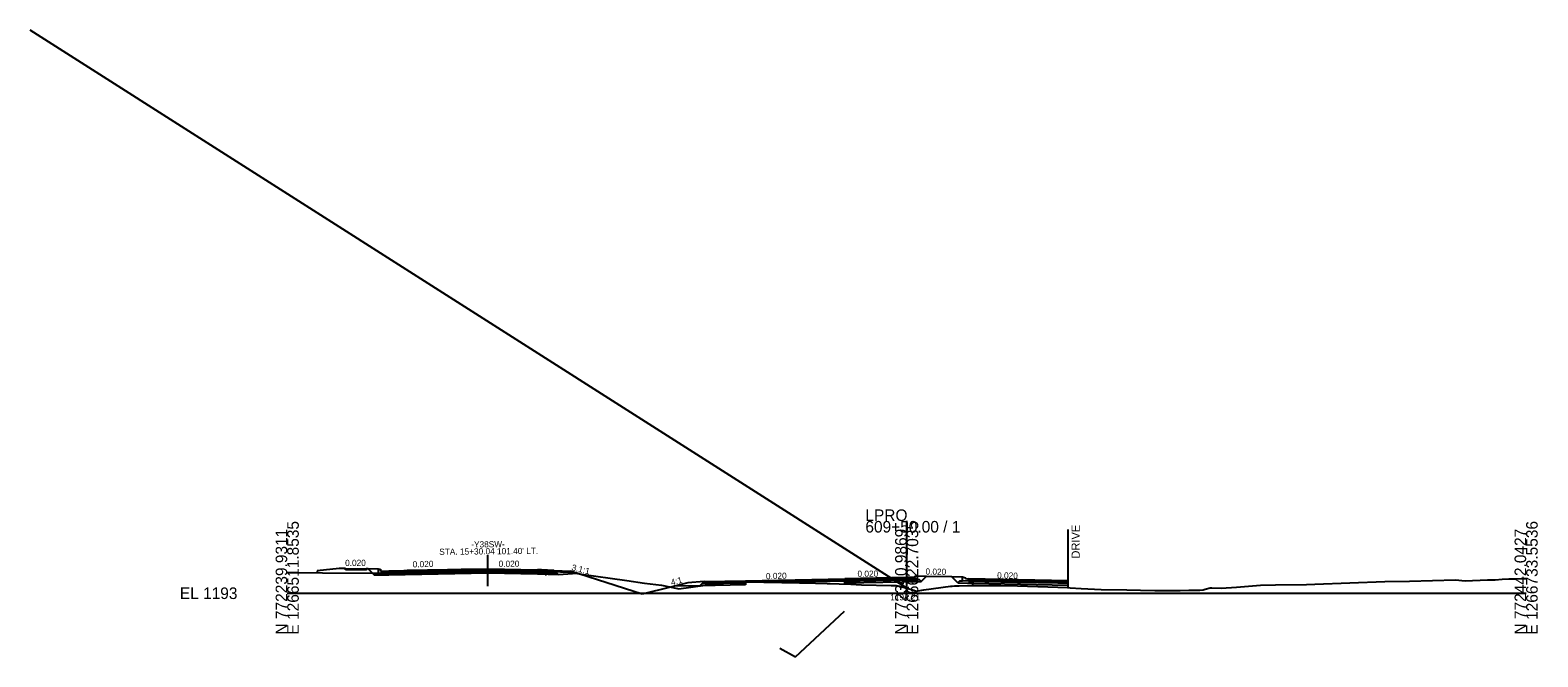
# Model space of a CAD drawing. Extents: x -3833 to 1267678, y -522 to 773248.
# Drawn here: x 1937.8 to 2302.8, y 484.6 to 636.3 of the extents above; entities that cross this region are included whole.
import ezdxf

# ---------------------------------------------------------------- set-up
doc = ezdxf.new("R2010")
doc.units = 0
for name, color, linetype in [('Exist Cross Section Cell', 7, 'Continuous'), ('Exist XS Center Line Elevation Label', 7, 'Continuous'), ('Exist XS Ground Line', 7, 'Continuous'), ('Prop CMT DNC', 7, 'Continuous'), ('Prop CMT Pvmt Course 1', 7, 'Continuous'), ('Prop CMT Pvmt Course 2', 7, 'Continuous'), ('Prop CMT Pvmt Course 3', 7, 'Continuous'), ('Prop CMT Pvmt Course 4', 7, 'Continuous'), ('Prop CMT Shld Paved Course 1', 7, 'Continuous'), ('Prop CMT Shld Paved Course 2', 7, 'Continuous'), ('Prop CMT Shld Paved Course 4', 7, 'Continuous'), ('Prop CMT Slope Fill', 7, 'Continuous'), ('Prop CMT Slope Grass', 7, 'Continuous'), ('Prop CMT Subgrade Earthwork', 7, 'Continuous'), ('Prop Conc 4in Sidewalk', 7, 'Continuous'), ('Prop Conc Curb and Gutter', 7, 'Continuous'), ('Prop Conc Island Cover', 7, 'Continuous'), ('Prop Corridor Mesh Bottom', 7, 'Continuous'), ('Prop XS Ditch Slope Text', 7, 'Continuous'), ('Prop XS Finish Grade', 7, 'Continuous'), ('Prop XS SE Text', 7, 'Continuous'), ('Prop XS Shear Point Element', 7, 'Continuous'), ('Prop XS Shear Point Label', 7, 'Continuous'), ('Scratch_Level_1', 7, 'Continuous'), ('Scratch_Level_5', 7, 'Continuous'), ('Scratch_Level_9', 7, 'Continuous')]:
    doc.layers.add(name, color=color, linetype=linetype)

msp = doc.modelspace()

# ---------------------------------------------------------------- linework, layer by layer
at = {"layer": 'Exist Cross Section Cell'}
for p, q in [((2150, 500), (2150, 517.49)), ((2000, 500), (2150, 500)), ((2150, 500), (2300, 500))]:
    msp.add_line(p, q, dxfattribs=at)
at = {"layer": 'Exist XS Ground Line'}
for p, q in [((2000, 505.03), (2008.54, 504.97)), ((2008.54, 504.97), (2021.79, 504.89)), ((2021.79, 504.89), (2029.03, 505.56)), ((2029.03, 505.56), (2038.85, 505.76)), ((2038.85, 505.76), (2042.16, 505.81)), ((2042.16, 505.81), (2042.8, 505.82)), ((2042.8, 505.82), (2043.29, 505.82)), ((2043.29, 505.82), (2043.6, 505.82)), ((2043.6, 505.82), (2046.76, 505.83)), ((2046.76, 505.83), (2048.98, 505.82)), ((2048.98, 505.82), (2061.18, 505.37)), ((2061.18, 505.37), (2068.67, 505.1)), ((2068.67, 505.1), (2069.2, 505)), ((2069.2, 505), (2070.66, 504.73)), ((2070.66, 504.73), (2082.23, 503.05)), ((2082.23, 503.05), (2086.51, 502.47)), ((2086.51, 502.47), (2090.63, 501.93)), ((2090.63, 501.93), (2094.47, 501.12)), ((2094.47, 501.12), (2094.85, 501.05)), ((2094.85, 501.05), (2104.7, 502.42)), ((2104.7, 502.42), (2105.39, 502.5)), ((2105.39, 502.5), (2107.57, 502.72)), ((2107.57, 502.72), (2110.72, 502.73)), ((2110.72, 502.73), (2111.94, 502.74)), ((2111.94, 502.74), (2115.42, 502.68)), ((2115.42, 502.68), (2124.07, 502.55)), ((2124.07, 502.55), (2127.9, 502.43)), ((2127.9, 502.43), (2136.48, 502.16)), ((2136.48, 502.16), (2139.04, 502.06)), ((2139.04, 502.06), (2146.21, 501.87)), ((2146.21, 501.87), (2146.58, 501.86)), ((2146.58, 501.86), (2147.47, 501.85)), ((2147.47, 501.85), (2148.24, 501.68)), ((2148.24, 501.68), (2148.58, 501.6)), ((2148.58, 501.6), (2150, 501.21)), ((2150, 501.21), (2151.76, 500.73)), ((2151.76, 500.73), (2152.31, 500.52)), ((2152.31, 500.52), (2154.18, 500.79)), ((2154.18, 500.79), (2160.62, 501.7)), ((2160.62, 501.7), (2161.03, 501.75)), ((2161.03, 501.75), (2161.62, 501.8)), ((2161.62, 501.8), (2162.71, 501.82)), ((2162.71, 501.82), (2164.75, 501.87)), ((2164.75, 501.87), (2172.8, 501.84)), ((2172.8, 501.84), (2176.84, 501.81)), ((2176.84, 501.81), (2186.61, 501.46)), ((2186.61, 501.46), (2188.98, 501.37)), ((2188.98, 501.37), (2189.6, 501.33)), ((2189.6, 501.33), (2192.22, 501.14)), ((2192.22, 501.14), (2197.11, 500.93)), ((2197.11, 500.93), (2203.28, 500.82)), ((2203.28, 500.82), (2206.64, 500.77)), ((2206.64, 500.77), (2210.13, 500.68)), ((2210.13, 500.68), (2213.67, 500.7)), ((2213.67, 500.7), (2216.23, 500.7)), ((2216.23, 500.7), (2218.3, 500.74)), ((2218.3, 500.74), (2219.36, 500.76)), ((2219.36, 500.76), (2220.97, 500.78)), ((2220.97, 500.78), (2221.78, 500.8)), ((2221.78, 500.8), (2222.31, 500.97)), ((2222.31, 500.97), (2223.46, 501.34)), ((2223.46, 501.34), (2223.88, 501.32)), ((2223.88, 501.32), (2226.14, 501.24)), ((2226.14, 501.24), (2229.88, 501.46)), ((2229.88, 501.46), (2235.66, 501.92)), ((2235.66, 501.92), (2239.29, 502.07)), ((2239.29, 502.07), (2246.81, 502.13)), ((2246.81, 502.13), (2248.8, 502.23)), ((2248.8, 502.23), (2265.81, 502.85)), ((2265.81, 502.85), (2271.76, 502.95)), ((2271.76, 502.95), (2282.88, 503.21)), ((2282.88, 503.21), (2285.25, 503.02)), ((2285.25, 503.02), (2290.68, 503.23)), ((2290.68, 503.23), (2292.48, 503.22)), ((2292.48, 503.22), (2294.2, 503.39)), ((2294.2, 503.39), (2295.81, 503.45)), ((2295.81, 503.45), (2297.71, 503.5)), ((2297.71, 503.5), (2298.81, 503.54)), ((2298.81, 503.54), (2300, 503.57))]:
    msp.add_line(p, q, dxfattribs=at)
at = {"layer": 'Prop CMT Pvmt Course 1'}
for p, q in [((2024.6, 505.45), (2048.6, 505.93)), ((2048.6, 505.68), (2024.6, 505.2)), ((2024.6, 505.45), (2024.6, 505.45)), ((2024.6, 505.2), (2024.6, 505.2)), ((2024.6, 505.2), (2024.6, 505.2)), ((2048.6, 505.93), (2060.6, 505.69)), ((2060.6, 505.44), (2048.6, 505.68)), ((2060.6, 505.69), (2060.6, 505.69)), ((2060.6, 505.69), (2060.6, 505.44)), ((2060.6, 505.44), (2060.6, 505.44)), ((2060.6, 505.44), (2060.6, 505.44)), ((2111, 503.04), (2135, 503.52)), ((2111, 502.79), (2111, 503.04)), ((2111, 503.04), (2111, 503.04)), ((2135, 503.52), (2135, 503.52)), ((2135, 503.52), (2135, 503.52)), ((2135, 503.27), (2135, 503.27)), ((2189.07, 503), (2165, 503.52)), ((2165, 503.52), (2165, 503.52)), ((2165, 503.52), (2165, 503.52)), ((2165, 503.52), (2165, 503.27)), ((2165, 503.27), (2165, 503.27)), ((2189.07, 503), (2189.07, 503))]:
    msp.add_line(p, q, dxfattribs=at)
at = {"layer": 'Prop CMT Pvmt Course 2'}
for p, q in [((2024.6, 504.86), (2024.6, 505.2)), ((2024.6, 505.2), (2024.6, 505.2)), ((2024.6, 504.86), (2024.6, 504.86)), ((2060.59, 505.1), (2060.59, 505.1)), ((2060.59, 505.1), (2060.59, 505.1)), ((2060.6, 505.44), (2060.6, 505.44)), ((2150, 503.57), (2135, 503.27)), ((2135, 503.27), (2135, 503.27)), ((2135, 502.94), (2150, 503.24)), ((2135, 502.94), (2135, 502.94)), ((2151.11, 503.55), (2150, 503.57)), ((2150, 503.57), (2150, 503.57)), ((2150, 503.24), (2150, 503.24)), ((2150, 503.24), (2150, 503.24)), ((2150, 503.24), (2151.11, 503.21)), ((2165, 502.94), (2165, 503.27)), ((2165, 503.27), (2165, 503.27)), ((2165, 502.94), (2165, 502.94))]:
    msp.add_line(p, q, dxfattribs=at)
at = {"layer": 'Prop CMT Pvmt Course 3'}
for p, q in [((2153.12, 503.25), (2152.62, 503.24)), ((2153.52, 502.85), (2153.12, 503.25))]:
    msp.add_line(p, q, dxfattribs=at)
at = {"layer": 'Prop CMT Pvmt Course 4'}
for p, q in [((2021.13, 504.34), (2021.6, 504.8)), ((2021.13, 504.34), (2021.13, 504.34)), ((2021.13, 504.34), (2021.13, 504.34)), ((2021.6, 504.8), (2022.1, 504.81)), ((2021.6, 504.8), (2021.6, 504.8)), ((2024.6, 504.86), (2048.59, 505.34)), ((2024.6, 504.86), (2024.6, 504.86)), ((2024.6, 504.41), (2024.6, 504.41)), ((2024.6, 504.41), (2024.6, 504.41)), ((2024.6, 504.41), (2024.6, 504.41)), ((2048.59, 505.34), (2060.59, 505.1)), ((2060.59, 505.1), (2060.59, 505.1)), ((2060.59, 505.1), (2060.59, 504.64)), ((2060.59, 504.64), (2060.59, 504.64)), ((2060.59, 504.64), (2060.59, 504.64)), ((2135, 502.48), (2135, 502.94)), ((2135, 502.94), (2135, 502.94)), ((2135, 502.94), (2135, 502.94)), ((2150, 503.24), (2150, 503.24)), ((2150, 503.24), (2150, 503.24)), ((2162.87, 502.98), (2162.39, 502.5)), ((2162.87, 502.98), (2163.49, 502.97)), ((2165, 502.94), (2165, 502.94)), ((2165, 502.94), (2165, 502.94)), ((2166, 503.5), (2166, 502.43)), ((2166, 502.43), (2189.07, 501.97))]:
    msp.add_line(p, q, dxfattribs=at)
at = {"layer": 'Prop CMT Shld Paved Course 1'}
for p, q in [((2061.57, 505.64), (2060.6, 505.69)), ((2060.6, 505.69), (2060.6, 505.44)), ((2060.6, 505.44), (2060.6, 505.44)), ((2060.6, 505.44), (2061.81, 505.38)), ((2064.6, 505.51), (2061.57, 505.64)), ((2061.81, 505.38), (2061.87, 505.38)), ((2061.87, 505.38), (2064.86, 505.25)), ((2064.86, 505.25), (2064.6, 505.51)), ((2149.99, 503.93), (2149.99, 503.93)), ((2100.74, 502.58), (2101, 502.84)), ((2111, 502.79), (2100.74, 502.58)), ((2101, 502.84), (2111, 503.04)), ((2111, 503.04), (2111, 502.79)), ((2150, 503.82), (2135, 503.52)), ((2135, 503.52), (2135, 503.52)), ((2135, 503.52), (2135, 503.27)), ((2151.15, 503.8), (2150, 503.82)), ((2150, 503.82), (2150, 503.82)), ((2150, 503.57), (2150, 503.57)), ((2150, 503.57), (2150, 503.57)), ((2165, 503.27), (2165, 503.52)), ((2165, 503.52), (2165, 503.52)), ((2165, 503.27), (2165, 503.27))]:
    msp.add_line(p, q, dxfattribs=at)
at = {"layer": 'Prop CMT Shld Paved Course 2'}
for p, q in [((2060.6, 505.44), (2060.59, 505.1)), ((2060.59, 505.1), (2060.59, 505.1)), ((2060.59, 505.1), (2062.02, 505.04)), ((2064.86, 505.25), (2061.81, 505.38)), ((2062.02, 505.04), (2062.16, 505.03)), ((2062.16, 505.03), (2065.21, 504.9)), ((2065.21, 504.9), (2064.86, 505.25)), ((2100.41, 502.25), (2100.74, 502.58)), ((2111, 502.46), (2100.41, 502.25)), ((2111, 502.79), (2111.94, 502.81)), ((2111, 502.79), (2111, 502.79)), ((2111, 502.79), (2111, 502.73)), ((2111.94, 502.74), (2111, 502.73)), ((2111.94, 502.81), (2115.42, 502.88)), ((2111.94, 502.81), (2111.94, 502.81)), ((2111.94, 502.81), (2111.94, 502.81)), ((2115.42, 502.68), (2111.94, 502.74)), ((2111.94, 502.74), (2111.94, 502.74)), ((2111.94, 502.74), (2111.94, 502.74)), ((2115.42, 502.88), (2124.07, 503.05)), ((2115.42, 502.88), (2115.42, 502.88)), ((2119.29, 502.62), (2115.42, 502.68)), ((2115.42, 502.68), (2115.42, 502.68)), ((2124.07, 502.72), (2119.29, 502.62)), ((2119.29, 502.62), (2119.29, 502.62)), ((2124.07, 503.05), (2127.9, 503.13)), ((2127.9, 502.79), (2124.07, 502.72)), ((2127.9, 503.13), (2135, 503.27)), ((2127.9, 503.13), (2127.9, 503.13)), ((2135, 502.94), (2127.9, 502.79)), ((2127.9, 502.79), (2127.9, 502.79)), ((2135, 503.27), (2135, 503.27)), ((2135, 503.27), (2135, 503.27)), ((2135, 503.27), (2135, 502.94)), ((2135, 502.94), (2135, 502.94)), ((2172.79, 503.1), (2165, 503.27)), ((2165, 503.27), (2165, 503.27)), ((2165, 502.94), (2172.8, 502.78)), ((2176.84, 503.02), (2172.79, 503.1)), ((2172.79, 503.1), (2172.79, 503.1)), ((2172.8, 502.78), (2172.8, 502.78)), ((2172.8, 502.78), (2176.84, 502.7)), ((2186.61, 502.81), (2176.84, 503.02)), ((2176.84, 503.02), (2176.84, 503.02)), ((2176.84, 503.02), (2176.84, 503.02)), ((2176.84, 502.7), (2176.84, 502.7)), ((2176.84, 502.7), (2176.84, 502.7)), ((2176.84, 502.7), (2186.61, 502.5)), ((2188.99, 502.76), (2186.61, 502.81)), ((2186.61, 502.81), (2186.61, 502.81)), ((2186.61, 502.5), (2186.61, 502.5)), ((2186.61, 502.5), (2189.07, 502.42)), ((2189.07, 502.75), (2188.99, 502.76)), ((2188.99, 502.76), (2188.99, 502.76)), ((2189.07, 502.75), (2189.07, 502.75)), ((2189.07, 502.42), (2189.07, 502.42)), ((2189.07, 502.42), (2189.07, 502.42))]:
    msp.add_line(p, q, dxfattribs=at)
at = {"layer": 'Prop CMT Shld Paved Course 4'}
for p, q in [((2060.59, 504.64), (2060.59, 504.64)), ((2062.44, 504.56), (2062.75, 504.55)), ((2065.7, 504.42), (2065.21, 504.9)), ((2099.94, 501.78), (2100.41, 502.25))]:
    msp.add_line(p, q, dxfattribs=at)
at = {"layer": 'Prop CMT Slope Grass'}
for p, q in [((2022.1, 505.83), (2019.59, 505.88)), ((2064.6, 505.51), (2068.6, 505.33)), ((2152.62, 504.23), (2154.84, 504.17)), ((2160.88, 504.02), (2163.49, 503.95)), ((2101, 502.84), (2097, 502.52))]:
    msp.add_line(p, q, dxfattribs=at)
at = {"layer": 'Prop CMT Subgrade Earthwork'}
for p, q in [((2019.59, 505.88), (2021.13, 504.34)), ((2024.6, 504.41), (2021.13, 504.34)), ((2048.6, 504.89), (2024.6, 504.41)), ((2060.59, 504.64), (2048.6, 504.89)), ((2065.7, 504.42), (2060.59, 504.64)), ((2070.23, 504.81), (2065.7, 504.42)), ((2153.52, 502.85), (2154.84, 504.17)), ((2162.39, 502.5), (2160.88, 504.02)), ((2099.94, 501.78), (2093.69, 501.69)), ((2111, 502), (2099.94, 501.78)), ((2111, 502.73), (2111, 502)), ((2135, 502.48), (2153.52, 502.85)), ((2135, 502.21), (2135, 502.48)), ((2162.39, 502.5), (2166, 502.43)), ((2166, 501.87), (2166, 502.43))]:
    msp.add_line(p, q, dxfattribs=at)
at = {"layer": 'Prop Conc 4in Sidewalk'}
for p, q in [((2014.09, 505.65), (2014.1, 505.99)), ((2019.11, 505.55), (2014.09, 505.65)), ((2014.1, 505.99), (2019.1, 505.89)), ((2019.1, 505.89), (2019.11, 505.55))]:
    msp.add_line(p, q, dxfattribs=at)
at = {"layer": 'Prop Conc Curb and Gutter'}
for p, q in [((2022.1, 504.81), (2022.1, 505.83)), ((2022.1, 505.83), (2022.6, 505.83)), ((2024.6, 504.86), (2022.1, 504.81)), ((2022.1, 504.81), (2022.1, 504.81)), ((2022.1, 504.81), (2022.1, 504.81)), ((2022.6, 505.83), (2022.6, 505.83)), ((2022.6, 505.83), (2022.6, 505.33)), ((2022.6, 505.33), (2024.6, 505.45)), ((2022.6, 505.33), (2022.6, 505.33)), ((2022.6, 505.33), (2022.6, 505.33)), ((2024.6, 505.45), (2024.6, 504.86)), ((2024.6, 504.86), (2024.6, 504.86)), ((2152.62, 504.23), (2151.86, 503.98)), ((2151.86, 503.98), (2151.86, 503.98)), ((2151.86, 503.98), (2151.86, 503.81)), ((2152.62, 503.25), (2152.62, 504.23)), ((2163.49, 502.97), (2163.49, 503.95)), ((2163.49, 503.95), (2163.49, 503.95)), ((2163.49, 503.95), (2163.49, 503.95)), ((2163.49, 503.95), (2164.25, 503.7)), ((2151.11, 503.8), (2151.11, 503.8)), ((2151.11, 503.8), (2151.11, 503.21)), ((2151.15, 503.8), (2151.11, 503.8)), ((2151.11, 503.21), (2152.62, 503.24)), ((2151.86, 503.81), (2151.15, 503.8)), ((2151.86, 503.81), (2151.86, 503.81)), ((2152.62, 503.24), (2152.62, 503.25)), ((2165, 502.94), (2163.49, 502.97)), ((2163.49, 502.97), (2163.49, 502.97)), ((2164.25, 503.7), (2164.25, 503.7)), ((2164.25, 503.7), (2164.25, 503.53)), ((2164.25, 503.53), (2165, 503.52)), ((2164.25, 503.53), (2164.25, 503.53)), ((2165, 503.52), (2165, 503.52)), ((2165, 503.52), (2165, 502.94))]:
    msp.add_line(p, q, dxfattribs=at)
at = {"layer": 'Prop Conc Island Cover'}
for p, q in [((2163.49, 503.95), (2163.49, 503.95)), ((2163.49, 503.95), (2163.49, 503.95)), ((2163.49, 503.7), (2163.49, 503.7)), ((2163.49, 503.7), (2163.49, 503.7))]:
    msp.add_line(p, q, dxfattribs=at)
at = {"layer": 'Prop Corridor Mesh Bottom'}
for p, q in [((2111, 503.04), (2111, 502.79)), ((2165, 503.52), (2165, 503.27))]:
    msp.add_line(p, q, dxfattribs=at)
at = {"layer": 'Prop XS Finish Grade'}
for p, q in [((2012.6, 506.02), (2007.26, 505.46)), ((2007.26, 505.46), (2007.26, 504.98)), ((2014.1, 505.99), (2012.6, 506.02)), ((2014.1, 505.99), (2019.1, 505.89)), ((2019.59, 505.88), (2019.1, 505.89)), ((2085.96, 499.76), (2068.6, 505.33)), ((2154.84, 504.17), (2160.88, 504.02)), ((2163.49, 503.95), (2163.49, 503.95)), ((2092.8, 501.47), (2085.96, 499.76)), ((2097, 502.52), (2092.8, 501.47))]:
    msp.add_line(p, q, dxfattribs=at)
at = {"layer": 'Prop XS Shear Point Element'}
for p, q in [((2189.07, 501.37), (2189.07, 515.41)), ((2048.6, 501.69), (2048.6, 509.18))]:
    msp.add_line(p, q, dxfattribs=at)
at = {"layer": 'Scratch_Level_1'}
msp.add_line((2150, 501.21), (1937.75, 636.27), dxfattribs=at)
at = {"layer": 'Scratch_Level_5'}
for p, q in [((2123.09, 484.61), (2134.94, 495.63)), ((2119.3, 486.71), (2123.09, 484.61))]:
    msp.add_line(p, q, dxfattribs=at)
at = {"layer": 'Scratch_Level_9'}
msp.add_lwpolyline([(2024.6, 505.45), (2024.6, 505.2)], dxfattribs=at)
msp.add_lwpolyline([(2024.6, 505.45), (2024.6, 505.2)], dxfattribs=at)

# ---------------------------------------------------------------- texts
at = {"layer": 'Exist Cross Section Cell'}
for s, p in [('LPRO', (2140, 517.49)), ('609+50.00 / 1', (2140, 514.69)), ('EL 1193', (1974, 498.6))]:
    msp.add_text(s, height=2.8, dxfattribs=at).set_placement(p)
for s, p in [('N 772239.9311', (2000, 490)), ('E 1266511.8535', (2002.8, 490)), ('N 772340.9869', (2150, 490)), ('E 1266622.7035', (2152.8, 490)), ('N 772442.0427', (2300, 490)), ('E 1266733.5536', (2302.8, 490))]:
    msp.add_text(s, height=2.8, rotation=90, dxfattribs=at).set_placement(p)
at = {"layer": 'Exist XS Center Line Elevation Label'}
msp.add_text('1194.21', height=1.5, dxfattribs=at).set_placement((2146.02, 498.29))
at = {"layer": 'Prop CMT DNC'}
for p in [(2111, 503.04), (2111, 503.04), (2135, 503.52), (2135, 503.52), (2151.86, 503.81), (2164.25, 503.53), (2165, 503.52), (2165, 503.52)]:
    msp.add_text('X', height=0.00025, dxfattribs=at).set_placement(p)
at = {"layer": 'Prop CMT Slope Fill'}
for p in [(2010.44, 505.48), (2022.6, 505.33), (2024.6, 505.45), (2048.6, 505.93), (2060.6, 505.69)]:
    msp.add_text('X', height=0.00025, dxfattribs=at).set_placement(p)
at = {"layer": 'Prop XS Ditch Slope Text'}
for s, rotation, p in [('3.1:1', 346.6717, (2068.75, 505.58)), ('4:1', 16.0788, (2093.12, 501.83))]:
    msp.add_text(s, height=1.5, rotation=rotation, dxfattribs=at).set_placement(p)
at = {"layer": 'Prop XS SE Text'}
for s, rotation, p in [('-Y38SW-', 0.5826, (2044.57, 511.06)), ('0.020', 0.2693, (2014.02, 506.59)), ('0.020', 1.397, (2030.4, 506.25)), ("STA. 15+30.04 101.40' LT.", 0.5826, (2036.82, 509.28)), ('0.020', 0.2693, (2051.2, 506.38)), ('0.020', 1.397, (2115.94, 503.38)), ('0.020', 0.2693, (2138.09, 503.97)), ('0.020', 358.8542, (2154.55, 504.52)), ('0.020', 358.8542, (2171.89, 503.59))]:
    msp.add_text(s, height=1.5, rotation=rotation, dxfattribs=at).set_placement(p)
at = {"layer": 'Prop XS Shear Point Label'}
msp.add_text('DRIVE', height=2, rotation=90, dxfattribs=at).set_placement((2191.92, 508.4))

doc.saveas('drawing.dxf')
